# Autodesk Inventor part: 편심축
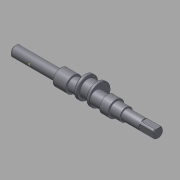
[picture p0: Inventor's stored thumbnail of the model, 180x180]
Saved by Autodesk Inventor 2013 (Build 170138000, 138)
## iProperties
Company: 한국ATC센터
Created: 2015-12
Part Number: 편심축
Document SubType Name: Modeling
Designer: mdu
Density: 7.86 g/cm^3
Mass: 232.042 g
Surface Area: 95.1312 cm^2
Volume: 29.5219 cm^3
Material: 강철, 연강
Author: mdu
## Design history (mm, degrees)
sketch "스케치1"
  geometry: L1 (-84.5, 0)-(84.5, 0); L2 (-84.5, 0)-(-84.5, 6); L3 (-84.5, 6)-(-30.5, 6); L4 (-30.5, 6)-(-30.5, 9.5); L5 (-30.5, 9.5)-(-15.5, 9.5); L6 (-15.5, 9.5)-(-15.5, 7.5); L7 (-15.5, 7.5)-(46.5, 7.5); L8 (84.5, 6)-(84.5, 0); L9 (34.5, 7.5)-(34.5, 9.5); L10 (34.5, 9.5)-(24.5, 9.5); L11 (24.5, 9.5)-(24.5, 7.5); L12 (46.5, 7.5)-(46.5, 6); L13 (46.5, 6)-(84.5, 6); 2 further points
  constraints: 26 end point, 6 parallel, 6 perpendicular, 2 point on line, 1 coincident, 1 horizontal, 1 midpoint
  dimensions: "d1" = 12 diameter of L3 L1; "d2" = 15 diameter of L7 L1; "d4" = 15 distance of L4.end L5.end; "d5" = 19 diameter of L5 L1; "d24" = 10 distance of L9.end L10.end; "d25" = 19 diameter of L10 L1; "d27" = 40 distance between parallel lines of L11 L6; "d28" = 54 distance of L2.end L3.end; "d29" = 50 distance between parallel lines of L8 L9; "d41" = 38 distance between parallel lines of L8 L12; "d42" = 12 diameter of L13 L1
revolve "회전1" stored, may be unused: angle "d6" = 90 deg
node "작업 평면1"
sketch "스케치2"
  geometry: C1 r 7.5 at (0, 0) reference; C2 r 12.5 at (0, 4.5); 1 further point
  constraints: 1 centre point, 1 vertical alignment
  dimensions: "d8" = 4.5 distance of point (0, 0) C2.centre; "d9" = 25 diameter of C2
extrude "돌출1" join sketch "스케치2" distance "d10" = 18; taper "d11" = 0 deg
chamfer "모따기1" distance "d12" = 1; stored, may be unused: second distance "d13" = 2, angle "d14" = 45 deg
chamfer "모따기2" distance "d15" = 0.5; stored, may be unused: second distance "d16" = 2, angle "d17" = 45 deg
node "작업 평면2"
sketch "스케치3"
  geometry: L1 (4, -2)-(18, -2); L2 (18, 2)-(4, 2); L3 (27, 5)-(27, -5) reference; A1 r 2 centre (18, 0) between (18, -2) and (18, 2); A2 r 2 centre (4, 0) between (4, 2) and (4, -2); 2 further points
  constraints: 4 end point, 4 point on circle, 4 tangent, 2 centre point, 1 horizontal, 1 horizontal alignment, 1 midpoint, 1 parallel
  dimensions: "d18" = 7 distance edge to line of A1 L3; "d19" = 4 distance between parallel lines of L2 L1; "d20" = 18 dimension on A1 A2
extrude "돌출2" cut sketch "스케치3" distance "d21" = 2.5; taper "d22" = 0 deg
revolve "회전2" stored, may be unused: angle "d26" = 90 deg
node "작업 평면3"
sketch "스케치10"
  geometry: L1 (-5, -5)-(5, -5); L2 (5, -5)-(5, 5); L3 (5, 5)-(-5, 5); L4 (-5, 5)-(-5, -5); L5 (-5, -5)-(5, 5); L6 (5, -5)-(-5, 5); C1 r 5 at (0, 0) reference; C2 r 6 at (0, 0) reference; A1 r 6 centre (0, 0) between (5, 3.317) and (3.317, 5); A2 r 6 centre (0, 0) between (5, -3.317) and (5, 3.317); A3 r 6 centre (0, 0) between (3.317, -5) and (5, -3.317); A4 r 6 centre (0, 0) between (-3.317, -5) and (3.317, -5); A5 r 6 centre (0, 0) between (-5, -3.317) and (-3.317, -5); A6 r 6 centre (0, 0) between (-5, 3.317) and (-5, -3.317); A7 r 6 centre (0, 0) between (-3.317, 5) and (-5, 3.317); A8 r 6 centre (0, 0) between (3.317, 5) and (-3.317, 5)
  constraints: 16 point on circle, 12 end point, 8 centre point, 8 point on line, 2 midpoint, 2 parallel, 2 tangent, 1 coincident, 1 concentric, 1 horizontal, 1 perpendicular
extrude "돌출4" cut sketch "스케치10" distance "d55" = 17; taper "d56" = 0 deg
sketch "스케치6"
  geometry: L1 (-83.5, -6)-(-30.5, -6) reference; L2 (-84.5, -5)-(-84.5, 5) reference; L3 (-83.5, 6)-(-30.5, 6) reference; L4 (-62.5, 6)-(-62.5, -6); L5 (-62.5, -6)-(-61, -6); L6 (-62.5, -4.5)-(-61, -6); L7 (-62.5, -6)-(-62.5, -4.5); 2 further points
  constraints: 8 end point, 4 point on line, 2 perpendicular, 1 coincident
  dimensions: "d43" = 22 distance between parallel lines of L4 L2; "d44" = 45 deg angle of L6 L7; "d45" = 3 diameter of L5.end L4
revolve "회전3" stored, may be unused: angle "d46" = 90 deg
node "작업점1"
node "작업 평면5"
sketch "스케치11"
  geometry: C1 r 12.5 at (0, 0) reference; C2 r 9.5 at (0, 0); 1 further point
  constraints: 1 centre point
  dimensions: "d57" = 3 radial gap between concentric circles of C1 C2
extrude "돌출5" cut sketch "스케치11" stored distance "d58" = 11; taper "d59" = 0 deg
fillet "모깎기1" dims "d60" = 0.3
chamfer "모따기4" distance "d61" = 0.5; stored, may be unused: second distance "d62" = 2, angle "d63" = 45 deg
node "솔리드1"
node "절단 모서리 투영2"
other parameters: "d7" = 8.5
